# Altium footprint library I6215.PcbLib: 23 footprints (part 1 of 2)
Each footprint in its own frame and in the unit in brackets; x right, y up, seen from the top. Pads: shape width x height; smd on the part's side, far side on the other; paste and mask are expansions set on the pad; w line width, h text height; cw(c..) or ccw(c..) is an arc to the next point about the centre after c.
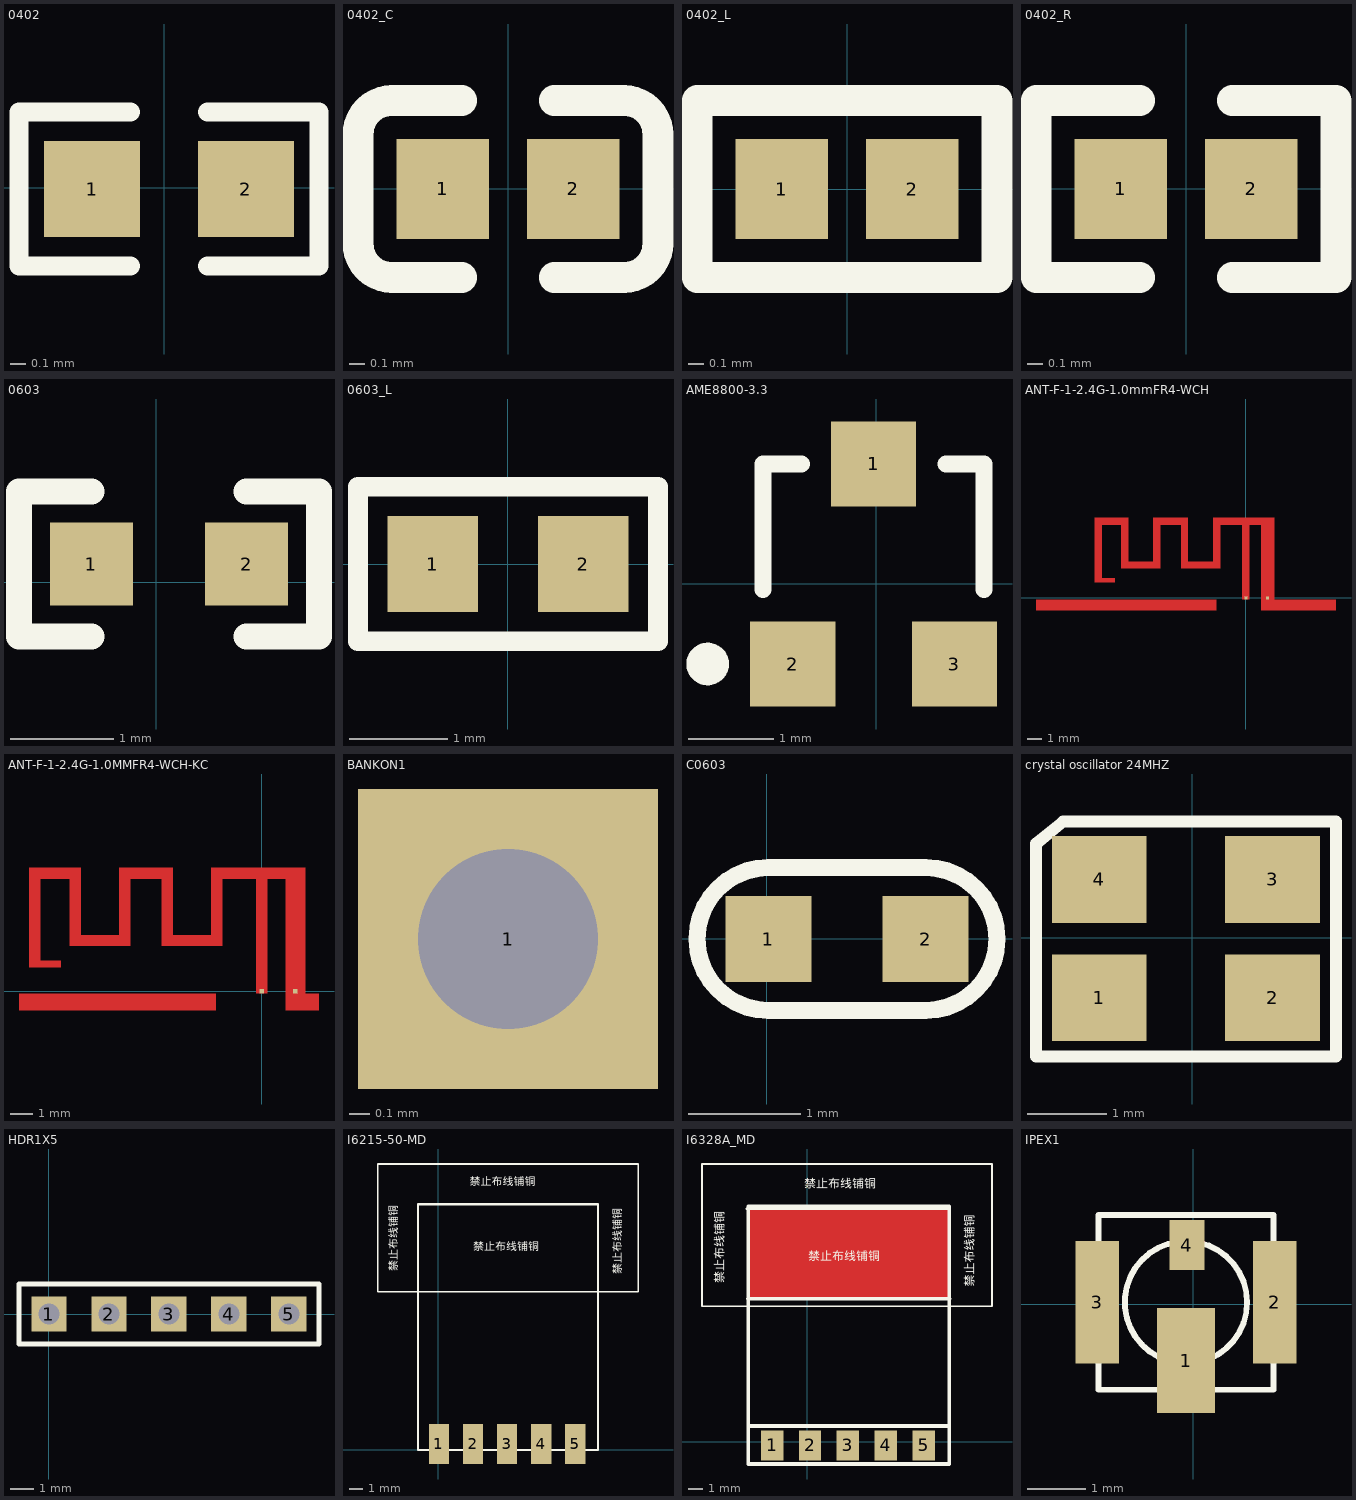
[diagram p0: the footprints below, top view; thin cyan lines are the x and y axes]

## 0402 [mm]
pads (2):
  rect 0.635x0.635 smd: 1(-0.475,-0.007) 2(0.541,-0.007)
Top Overlay:
  lines w0.127: -0.221,-0.515 -0.958,-0.515 -0.958,0.501 -0.221,0.501 ; 0.287,-0.515 1.023,-0.515 1.023,0.501 0.287,0.501

## 0402_C [mm]
height 1.3
pads (2):
  rect 0.6x0.65 smd mask+0.051: 1(-0.425,0) 2(0.425,0)
Top Overlay:
  lines w0.2: -0.755,-0.575 cw(c-0.755,-0.355) -0.975,-0.355 -0.975,0.355 cw(c-0.755,0.355) -0.755,0.575 ; -0.75,-0.575 -0.3,-0.575 ; -0.75,0.575 -0.3,0.575 ; 0.3,-0.575 0.75,-0.575 ; 0.3,0.575 0.75,0.575 ; 0.755,-0.575 ccw(c0.755,-0.355) 0.975,-0.355 0.975,0.355 ccw(c0.755,0.355) 0.755,0.575
3D body: height 0.2, standoff 0, extent -0.483,-0.3 0.518,0.3

## 0402_L [mm]
pads (2):
  rect 0.6x0.65 smd mask+0.051: 1(-0.425,0) 2(0.425,0)
Top Overlay:
  lines w0.2: -0.975,-0.575 0.975,-0.575 0.975,0.575 -0.975,0.575 -0.975,-0.575
3D body: height 0.36, standoff -0.01, extent -0.512,-0.262 0.538,0.263

## 0402_R [mm]
height 1.3
pads (2):
  rect 0.6x0.65 smd mask+0.051: 1(-0.425,0) 2(0.425,0)
Top Overlay:
  lines w0.2: -0.3,-0.575 -0.975,-0.575 -0.975,0.575 -0.3,0.575 ; 0.3,-0.575 0.975,-0.575 0.975,0.575 0.3,0.575
3D body: height 0.41, standoff 0, extent -0.575,-0.275 0.575,0.275

## 0603 [mm]
pads (2):
  rect 0.8x0.8 smd: 1(-0.626,0.174) 2(0.874,0.174)
Top Overlay:
  lines w0.254: -0.626,-0.526 -1.326,-0.526 -1.326,0.874 -0.626,0.874 ; 0.874,-0.526 1.574,-0.526 1.574,0.874 0.874,0.874

## 0603_L [mm]
height 1.35
pads (2):
  rect 0.93x0.98 smd: 1(-0.77,0) 2(0.77,0)
Top Overlay:
  lines w0.2: -1.535,-0.79 1.535,-0.79 1.535,0.79 -1.535,0.79 -1.535,-0.79
3D body: height 0.46, standoff -0.01, extent -0.824,-0.412 0.824,0.413

## AME8800-3.3 [mm]
height 1.3
pads (3):
  rect 1x1 smd: 1(-0.033,1.406) 2(-0.983,-0.944) 3(0.917,-0.944)
Top Overlay:
  circle w0.25: c-1.983,-0.944 r0.125
  lines w0.2: -1.333,-0.069 -1.333,1.406 -0.883,1.406 ; 0.817,1.406 1.267,1.406 1.267,-0.069

## ANT-F-1-2.4G-1.0mmFR4-WCH [mm]
pads (2):
  rect 0.2x0.2 smd mask+0: 1(0,0) 2(1.483,0)
Top Layer:
  region: -9.86,5.18 -10.36,5.18 -10.36,1.06 -9.86,1.06
  region: -8.06,5.5 -10.36,5.5 -10.36,5 -8.06,5
  region: -8.06,5.18 -8.56,5.18 -8.56,2 -8.06,2
  region: -5.875,2.5 -8.364,2.5 -8.364,2 -5.875,2
  region: -5.86,5.18 -6.36,5.18 -6.36,2 -5.86,2
  region: -3.96,5.5 -6.36,5.5 -6.36,5 -3.96,5
  region: -3.96,5.18 -4.46,5.18 -4.46,2 -3.96,2
  region: -1.85,2.5 -4.39,2.5 -4.39,2 -1.85,2
  region: -1.76,5.18 -2.26,5.18 -2.26,2 -1.76,2
  region: 1.94,5.5 -2.26,5.5 -2.26,5 1.94,5
  region: 1.94,5.205 1.04,5.205 1.04,-0.1 1.94,-0.1
  region: 0.24,5.231 -0.26,5.231 -0.26,-0.1 0.24,-0.1
  region: -8.96,1.36 -10.36,1.36 -10.36,1.06 -8.96,1.06
  rectangle: -14.378,-0.863 -2.035,-0.1
  rectangle: 1.04,-0.863 6.163,-0.1
Mechanical 13:
  text "GND" at -8.427,-1.447 h0.89
  text "GND" at 1.88,-1.447 h0.89
  text "适用FR4板材，1.0mm板厚，封装未开窗，建议天线开窗。技术咨询 tech@wch.cn" at -10.487,-4.419 h0.4

## ANT-F-1-2.4G-1.0MMFR4-WCH-KC [mm]
pads (2):
  rect 0.2x0.2 smd mask+0: 1(0,0) 2(1.483,0)
Top Layer:
  region: 1.94,5.205 1.04,5.205 1.04,-0.1 1.94,-0.1
  region: 0.24,5.231 -0.26,5.231 -0.26,-0.1 0.24,-0.1
  region: 1.94,5.5 -2.26,5.5 -2.26,5 1.94,5
  region: -1.76,5.18 -2.26,5.18 -2.26,2 -1.76,2
  region: -1.85,2.5 -4.39,2.5 -4.39,2 -1.85,2
  region: -3.96,5.18 -4.46,5.18 -4.46,2 -3.96,2
  region: -3.96,5.5 -6.36,5.5 -6.36,5 -3.96,5
  region: -5.86,5.18 -6.36,5.18 -6.36,2 -5.86,2
  region: -5.875,2.5 -8.364,2.5 -8.364,2 -5.875,2
  region: -8.06,5.18 -8.56,5.18 -8.56,2 -8.06,2
  region: -8.06,5.5 -10.36,5.5 -10.36,5 -8.06,5
  region: -9.86,5.18 -10.36,5.18 -10.36,1.06 -9.86,1.06
  region: -8.955,1.36 -10.355,1.36 -10.355,1.06 -8.955,1.06
  rectangle: 1.04,-0.863 2.54,-0.1
  rectangle: -10.814,-0.863 -2.035,-0.1
Top Solder:
  region: -8.06,5.18 -8.56,5.18 -8.56,2 -8.06,2
  region: -5.875,2.5 -8.364,2.5 -8.364,2 -5.875,2
  region: -5.86,5.18 -6.36,5.18 -6.36,2 -5.86,2
  region: -3.96,5.5 -6.36,5.5 -6.36,5 -3.96,5
  region: -3.96,5.18 -4.46,5.18 -4.46,2 -3.96,2
  region: -1.85,2.5 -4.39,2.5 -4.39,2 -1.85,2
  region: -1.76,5.18 -2.26,5.18 -2.26,2 -1.76,2
  region: 1.94,5.5 -2.26,5.5 -2.26,5 1.94,5
  region: 0.24,5.231 -0.26,5.231 -0.26,-0.1 0.24,-0.1
  region: 1.94,5.205 1.04,5.205 1.04,-0.1 1.94,-0.1
  region: -9.86,5.184 -10.36,5.184 -10.36,1.064 -9.86,1.064
  region: -8.06,5.5 -10.36,5.5 -10.36,5 -8.06,5
  region: -8.96,1.36 -10.36,1.36 -10.36,1.06 -8.96,1.06

## BANKON1 [mm]
height 1.3
pads (1):
  rect 1.5x1.5 hole 0.9: 1(1.092,-3.15)

## C0603 [mil]
height 62.99
pads (2):
  rect 30x30 smd: 1(0.64,-0.09) 2(55.63,-0.09)
Top Overlay:
  lines w6: -24.36,-0.09 ccw(c0.64,-0.09) 0.63,-25.09 55.63,-25.09 ccw(c55.63,-0.09) 80.63,-0.09 ccw(c55.63,-0.09) 55.63,24.91 0.64,24.91 ccw(c0.64,-0.09) -24.36,-0.09

## crystal oscillator 24MHZ [mm]
height 1.3
pads (4):
  rect 1.2x1.1 smd: 1(-1.181,-0.762) 2(1.019,-0.762) 3(1.019,0.738) 4(-1.181,0.738)
Top Overlay:
  lines w0.152: -1.981,-1.507 -1.981,1.193 -1.636,1.473 1.824,1.473 1.824,-1.507 -1.981,-1.507

## HDR1X5 [mm] "Connector; Header; 6 Position"
pads (5):
  rect 1.5x1.5 hole 0.9: 1(0,0) 2(2.54,0) 3(5.08,0) 4(7.62,0) 5(10.16,0)
Top Overlay:
  lines w0.2: -1.27,-1.27 -1.27,1.27 11.433,1.27 11.433,-1.27 -1.27,-1.27

## I6215-50-MD [mm]
pads (5):
  rect 1.5x3 smd: 1(0.046,0.421) 2(2.586,0.421) 3(5.126,0.421) 4(7.666,0.421) 5(10.206,0.421)
Top Overlay:
  lines w0.127: -4.529,11.781 -4.529,21.278 -4.524,21.283 14.905,21.283 ; -4.526,11.757 -1.529,11.757 14.852,11.757 14.854,11.759 ; 14.907,11.759 14.907,21.255
  lines w0.152: -1.529,-0.028 11.907,-0.028 11.907,18.283 -1.529,18.283 -1.529,-0.028
  text "禁止布线铺铜" at 2.332,19.479 h1.02
  text "禁止布线铺铜" at 2.586,14.628 h1.02
  text "禁止布线铺铜" at 13.863,13.053 h1.02
  text "禁止布线铺铜" at -2.85,13.281 h1.02

## I6328A_MD [mm]
pads (5):
  rect 1.5x2 smd: 1(-2.368,-0.229) 2(0.172,-0.229) 3(2.712,-0.229) 4(5.252,-0.229) 5(7.792,-0.229)
Top Layer:
  pour cut-out: -3.943,15.769 9.494,15.773 9.494,9.599 -3.943,9.599
Bottom Layer:
  pour cut-out: -3.968,15.769 9.519,15.773 9.519,9.599 -3.968,9.599
Top Overlay:
  lines w0.127: -7.069,9.114 -7.069,18.611 -7.064,18.616 12.365,18.616 ; -7.066,9.09 -4.069,9.09 12.312,9.09 12.314,9.092 ; 12.367,9.092 12.367,18.588
  lines w0.152: -4.069,15.616 9.367,15.616
  lines w0.254: -3.981,9.594 9.514,9.594 ; -3.899,1.062 9.434,1.062 ; 9.494,-1.473 -3.957,-1.473 -3.957,15.757 -3.943,15.771 9.494,15.771 9.494,-1.439
  text "禁止布线铺铜" at -5.39,10.614 h1.02
  text "禁止布线铺铜" at 11.323,10.386 h1.02
  text "禁止布线铺铜" at 0.046,11.961 h1.02
  text "禁止布线铺铜" at -0.208,16.812 h1.02
Keep-Out Layer:
  lines w0.152: -3.943,-0.229 -3.943,15.771 9.494,15.771 9.494,-0.229

## IPEX1 [mm]
height 6
pads (4):
  rect 1x1.8 smd: 1(-0.124,-0.968)
  rect 0.75x2.1 smd: 2(1.401,0.032) 3(-1.649,0.032)
  rect 0.6x0.85 smd: 4(-0.109,1.016)
Top Overlay:
  circle w0.102: c-0.124,0.032 r1.05
  lines w0.102: -1.624,-1.468 1.376,-1.468 1.376,1.532 -1.624,1.532 -1.624,-1.468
